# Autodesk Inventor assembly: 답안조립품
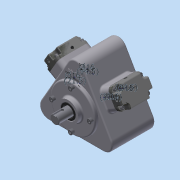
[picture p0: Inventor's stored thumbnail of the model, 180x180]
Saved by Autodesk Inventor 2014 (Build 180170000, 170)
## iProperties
Created: 2015-06
Part Number: 답안조립품
Document SubType Name: Assembly
Designer: Administrator
Mass: 5318.58 g
Surface Area: 2414.93 cm^2
Volume: 1564.62 cm^3
Density: 3.39928 g/cm^3
Author: Administrator
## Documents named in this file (20)
- C:\Users\Administrator\Desktop\350605V1049\답안조립품.iam
- C:\Users\Administrator\Desktop\350605V1049\본체.ipt
- C:\Users\Administrator\Desktop\350605V1049\베어링 NA 4904.ipt
- 베어링 NA 4904.ipt
- C:\Users\Administrator\Desktop\350605V1049\앞커버.ipt
- C:\Users\Administrator\Desktop\350605V1049\편심축.ipt
- C:\Users\Administrator\Desktop\350605V1049\M6x0.7x20.ipt
- M6x0.7x20.ipt
- C:\Users\Administrator\Desktop\350605V1049\오일실.ipt
- 오일실.ipt
- C:\Users\Administrator\Desktop\350605V1049\헤더커버.ipt
- 헤더커버.ipt
- C:\Users\Administrator\Desktop\350605V1049\부시.ipt
- C:\Users\Administrator\Desktop\350605V1049\M4x0.5x16.ipt
- M4x0.5x16.ipt
- C:\Users\Administrator\Desktop\350605V1049\슬라이드.ipt
- C:\Users\Administrator\Desktop\350605V1049\8-가변스프링.ipt
- C:\Users\Administrator\Desktop\350605V1049\9-가변스프링.ipt
- C:\Users\Administrator\Desktop\350605V1049\10-가변스프링.ipt
- C:\Users\Administrator\Desktop\350605V1049\11-가변스프링.ipt
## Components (18 placed, 7 different names)
1. 헤더커버:1
2. 헤더커버:2
3. 8-가변스프링:1
4. 9-가변스프링:1
5. 10-가변스프링:1
6. 11-가변스프링:1
7. M6x0.7x20:1
8. M6x0.7x20:2
9. M6x0.7x20:3
10. M6x0.7x20:4
11. M4x0.5x16:1
12. M4x0.5x16:3
13. M4x0.5x16:4
14. M4x0.5x16:5
15. M4x0.5x16:2
16. M4x0.5x16:6
17. M4x0.5x16:7
18. M4x0.5x16:8
